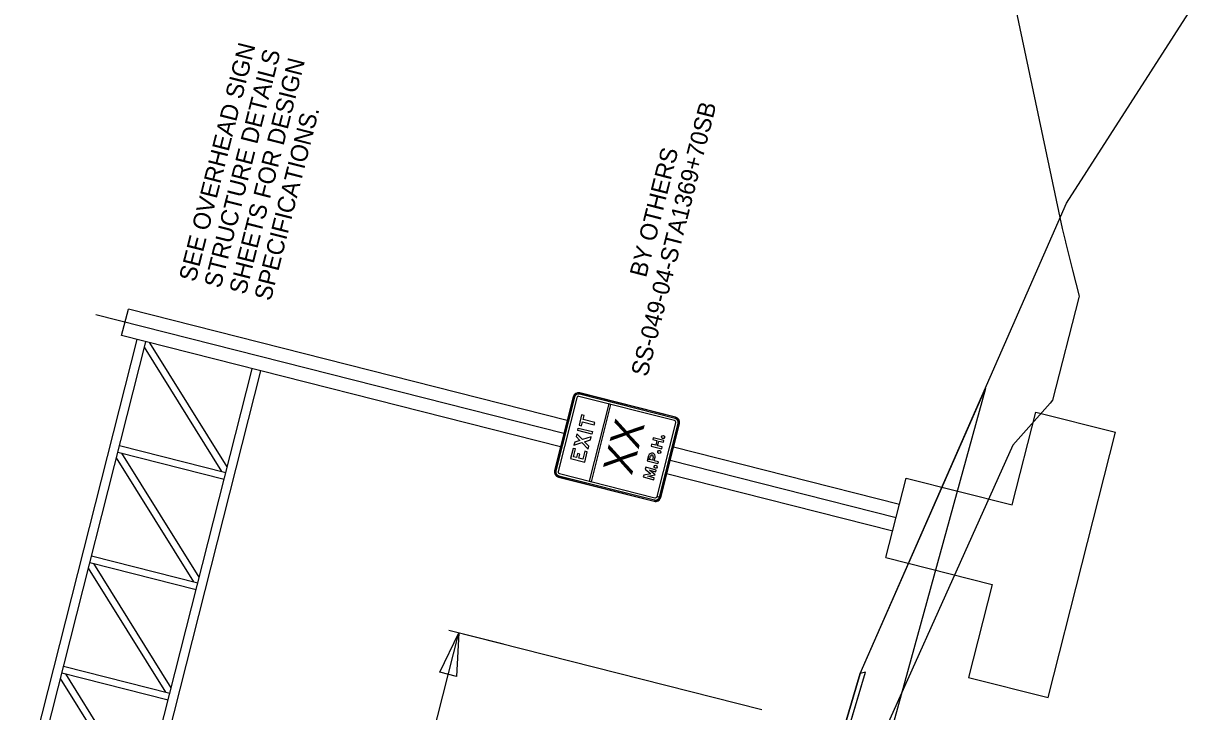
# Model space of a CAD drawing. Extents: x 670003 to 670131, y 737835 to 738003.
# Drawn here: x 670073.43 to 670116.21, y 737915.28 to 737940.42 of the extents above; entities that cross this region are included whole.
import ezdxf

# ---------------------------------------------------------------- set-up
doc = ezdxf.new("R2010")
doc.units = 0
for name, color, linetype in [('R_Alt Surface', 7, 'Continuous'), ('R_Exist Surface', 7, 'Continuous'), ('R_SIGN', 7, 'Continuous'), ('R_SIGN_ANNOT', 7, 'Continuous')]:
    doc.layers.add(name, color=color, linetype=linetype)

msp = doc.modelspace()

# ---------------------------------------------------------------- linework, layer by layer
at = {"layer": 'R_Alt Surface'}
msp.add_lwpolyline([(670102.433, 737911.395), (670103.999, 737916.672), (670111.535, 737933.847), (670116.209, 737941.135)], dxfattribs=at)
for points in [[(670108.568, 737927.085), (670102.543, 737905.177), (670102.018, 737905.311), (670102.212, 737905.963), (670100.911, 737905.679), (670104.184, 737916.713), (670103.999, 737916.672)], [(670102.433, 737911.395), (670102.595, 737911.354), (670104.184, 737916.713), (670103.999, 737916.672)]]:
    msp.add_lwpolyline(points, close=True, dxfattribs=at)
at = {"layer": 'R_Exist Surface'}
msp.add_lwpolyline([(670106.502, 737955.962), (670111.377, 737932.926), (670111.492, 737932.435), (670111.496, 737932.423), (670111.755, 737931.399), (670111.997, 737930.453), (670111.984, 737930.402), (670111.022, 737926.655), (670110.931, 737926.545), (670109.565, 737925.004), (670103.151, 737910.71), (670100.52, 737904.756), (670095.739, 737887.589), (670089.988, 737866.935), (670089.122, 737859.498), (670089.026, 737858.686), (670088.894, 737857.106), (670088.049, 737846.436), (670087.716, 737842.296), (670087.676, 737841.874), (670087.513, 737841.506), (670087.265, 737840.962)], dxfattribs=at)
at = {"layer": 'R_SIGN'}
for p, q in [((670093.172, 737925.432), (670076.077, 737929.768)), ((670077.021, 737929.012), (670077.267, 737929.982)), ((670093.295, 737925.916), (670077.267, 737929.982)), ((670073.434, 737912.507), (670077.583, 737928.87)), ((670093.049, 737924.947), (670077.021, 737929.012)), ((670073.757, 737912.425), (670077.906, 737928.788)), ((670080.683, 737924.049), (670077.855, 737928.586)), ((670080.874, 737924.216), (670078.046, 737928.752)), ((670077.635, 737911.442), (670081.784, 737927.804)), ((670077.951, 737911.332), (670082.107, 737927.722)), ((670093.514, 737926.778), (670092.831, 737924.086)), ((670093.522, 737926.776), (670092.839, 737924.084)), ((670093.562, 737926.765), (670092.879, 737924.074)), ((670093.643, 737926.745), (670092.96, 737924.053)), ((670093.522, 737926.776), (670093.522, 737926.776)), ((670097.214, 737925.907), (670093.724, 737926.793)), ((670097.234, 737925.988), (670093.744, 737926.873)), ((670093.754, 737926.913), (670093.754, 737926.913)), ((670097.244, 737926.028), (670093.754, 737926.913)), ((670097.246, 737926.036), (670093.756, 737926.921)), ((670094.812, 737926.517), (670094.097, 737923.697)), ((670094.812, 737926.517), (670094.097, 737923.697)), ((670094.812, 737926.517), (670094.097, 737923.697)), ((670094.178, 737923.676), (670094.893, 737926.496)), ((670094.178, 737923.676), (670094.893, 737926.496)), ((670094.178, 737923.676), (670094.893, 737926.496)), ((670094.893, 737926.496), (670094.812, 737926.517)), ((670094.893, 737926.496), (670094.812, 737926.517)), ((670094.893, 737926.496), (670094.812, 737926.517)), ((670097.246, 737926.036), (670094.885, 737926.634)), ((670097.244, 737926.028), (670097.244, 737926.028)), ((670109.551, 737922.825), (670110.411, 737926.218)), ((670110.411, 737926.218), (670113.319, 737925.48)), ((670096.58, 737923.136), (670097.262, 737925.827)), ((670096.66, 737923.116), (670097.343, 737925.807)), ((670096.701, 737923.105), (670097.383, 737925.796)), ((670096.709, 737923.103), (670097.391, 737925.794)), ((670097.383, 737925.796), (670097.383, 737925.796)), ((670110.861, 737915.787), (670113.319, 737925.48)), ((670076.884, 737924.755), (670080.761, 737923.771)), ((670076.945, 737924.997), (670080.822, 737924.014)), ((670079.851, 737920.183), (670077.023, 737924.719)), ((670096.439, 737924.583), (670096.408, 737924.459)), ((670105.428, 737922.839), (670097.173, 737924.933)), ((670079.66, 737920.016), (670076.833, 737924.553)), ((670096.476, 737924.441), (670096.507, 737924.566)), ((670105.305, 737922.355), (670097.05, 737924.448)), ((670092.839, 737924.084), (670092.839, 737924.084)), ((670092.976, 737923.845), (670096.466, 737922.959)), ((670092.978, 737923.852), (670092.978, 737923.853)), ((670092.978, 737923.852), (670096.468, 737922.967)), ((670092.988, 737923.893), (670096.478, 737923.007)), ((670093.009, 737923.973), (670096.498, 737923.088)), ((670105.182, 737921.87), (670096.927, 737923.964)), ((670104.936, 737920.901), (670105.673, 737923.809)), ((670105.673, 737923.809), (670109.551, 737922.825)), ((670094.097, 737923.697), (670094.178, 737923.676)), ((670094.097, 737923.697), (670094.178, 737923.676)), ((670094.097, 737923.697), (670094.178, 737923.676)), ((670096.468, 737922.967), (670096.468, 737922.967)), ((670096.66, 737923.115), (670096.579, 737923.135)), ((670096.58, 737923.136), (670096.66, 737923.116)), ((670096.701, 737923.105), (670096.7, 737923.105)), ((670096.709, 737923.102), (670096.701, 737923.105)), ((670096.701, 737923.105), (670096.709, 737923.103)), ((670075.922, 737920.964), (670079.8, 737919.981)), ((670104.936, 737920.901), (670108.813, 737919.917)), ((670078.637, 737915.983), (670075.81, 737920.52)), ((670075.861, 737920.722), (670079.738, 737919.738)), ((670078.828, 737916.149), (670076.001, 737920.686)), ((670108.813, 737919.917), (670107.953, 737916.525)), ((670074.9, 737916.931), (670078.777, 737915.948)), ((670077.615, 737911.95), (670074.787, 737916.487)), ((670074.838, 737916.688), (670078.716, 737915.705)), ((670077.806, 737912.116), (670074.978, 737916.653)), ((670107.953, 737916.525), (670110.861, 737915.787))]:
    msp.add_line(p, q, dxfattribs=at)
for points in [[(670093.818, 737925.72), (670093.854, 737925.864), (670094.281, 737925.756), (670094.303, 737925.844), (670093.877, 737925.953), (670093.913, 737926.097), (670093.823, 737926.119), (670093.727, 737925.743)], [(670093.818, 737925.72), (670093.854, 737925.864), (670094.281, 737925.756), (670094.303, 737925.844), (670093.877, 737925.953), (670093.913, 737926.097), (670093.823, 737926.119), (670093.727, 737925.743)], [(670093.818, 737925.72), (670093.854, 737925.864), (670094.281, 737925.756), (670094.303, 737925.844), (670093.877, 737925.953), (670093.913, 737926.097), (670093.823, 737926.119), (670093.727, 737925.743)], [(670094.195, 737925.417), (670093.678, 737925.548), (670093.7, 737925.637), (670094.217, 737925.506)], [(670094.195, 737925.417), (670093.678, 737925.548), (670093.7, 737925.637), (670094.217, 737925.506)], [(670094.195, 737925.417), (670093.678, 737925.548), (670093.7, 737925.637), (670094.217, 737925.506)], [(670094.056, 737924.869), (670094.082, 737924.974), (670093.926, 737925.137), (670094.141, 737925.206), (670094.168, 737925.311), (670093.855, 737925.211), (670093.647, 737925.428), (670093.621, 737925.323), (670093.758, 737925.18), (670093.569, 737925.119), (670093.542, 737925.014), (670093.829, 737925.106)], [(670094.056, 737924.869), (670094.082, 737924.974), (670093.926, 737925.137), (670094.141, 737925.206), (670094.168, 737925.311), (670093.855, 737925.211), (670093.647, 737925.428), (670093.621, 737925.323), (670093.758, 737925.18), (670093.569, 737925.119), (670093.542, 737925.014), (670093.829, 737925.106)], [(670094.056, 737924.869), (670094.082, 737924.974), (670093.926, 737925.137), (670094.141, 737925.206), (670094.168, 737925.311), (670093.855, 737925.211), (670093.647, 737925.428), (670093.621, 737925.323), (670093.758, 737925.18), (670093.569, 737925.119), (670093.542, 737925.014), (670093.829, 737925.106)], [(670096.571, 737925.179), (670096.527, 737925.005), (670096.375, 737925.043), (670096.359, 737924.977), (670096.746, 737924.878), (670096.763, 737924.945), (670096.595, 737924.987), (670096.639, 737925.162), (670096.807, 737925.119), (670096.824, 737925.185), (670096.436, 737925.283), (670096.42, 737925.217)], [(670096.571, 737925.179), (670096.527, 737925.005), (670096.375, 737925.043), (670096.359, 737924.977), (670096.746, 737924.878), (670096.763, 737924.945), (670096.595, 737924.987), (670096.639, 737925.162), (670096.807, 737925.119), (670096.824, 737925.185), (670096.436, 737925.283), (670096.42, 737925.217)], [(670096.571, 737925.179), (670096.527, 737925.005), (670096.375, 737925.043), (670096.359, 737924.977), (670096.746, 737924.878), (670096.763, 737924.945), (670096.595, 737924.987), (670096.639, 737925.162), (670096.807, 737925.119), (670096.824, 737925.185), (670096.436, 737925.283), (670096.42, 737925.217)], [(670093.938, 737924.785), (670093.865, 737924.497), (670093.721, 737924.534), (670093.76, 737924.686), (670093.669, 737924.709), (670093.631, 737924.557), (670093.529, 737924.583), (670093.602, 737924.871), (670093.512, 737924.893), (670093.416, 737924.517), (670093.933, 737924.386), (670094.029, 737924.762)], [(670093.938, 737924.785), (670093.865, 737924.497), (670093.721, 737924.534), (670093.76, 737924.686), (670093.669, 737924.709), (670093.631, 737924.557), (670093.529, 737924.583), (670093.602, 737924.871), (670093.512, 737924.893), (670093.416, 737924.517), (670093.933, 737924.386), (670094.029, 737924.762)], [(670093.938, 737924.785), (670093.865, 737924.497), (670093.721, 737924.534), (670093.76, 737924.686), (670093.669, 737924.709), (670093.631, 737924.557), (670093.529, 737924.583), (670093.602, 737924.871), (670093.512, 737924.893), (670093.416, 737924.517), (670093.933, 737924.386), (670094.029, 737924.762)], [(670096.243, 737923.874), (670096.505, 737923.925), (670096.299, 737924.095), (670096.533, 737924.036), (670096.55, 737924.102), (670096.162, 737924.201), (670096.145, 737924.134), (670096.349, 737923.965), (670096.089, 737923.913), (670096.072, 737923.847), (670096.46, 737923.748), (670096.477, 737923.815)], [(670096.243, 737923.874), (670096.505, 737923.925), (670096.299, 737924.095), (670096.533, 737924.036), (670096.55, 737924.102), (670096.162, 737924.201), (670096.145, 737924.134), (670096.349, 737923.965), (670096.089, 737923.913), (670096.072, 737923.847), (670096.46, 737923.748), (670096.477, 737923.815)], [(670096.243, 737923.874), (670096.505, 737923.925), (670096.299, 737924.095), (670096.533, 737924.036), (670096.55, 737924.102), (670096.162, 737924.201), (670096.145, 737924.134), (670096.349, 737923.965), (670096.089, 737923.913), (670096.072, 737923.847), (670096.46, 737923.748), (670096.477, 737923.815)]]:
    msp.add_lwpolyline(points, close=True, dxfattribs=at)
for points in [[(670096.27, 737924.626), (670096.221, 737924.435), (670096.609, 737924.337), (670096.626, 737924.403), (670096.476, 737924.441)], [(670096.27, 737924.626), (670096.238, 737924.502), (670096.306, 737924.484), (670096.338, 737924.609)], [(670096.27, 737924.626), (670096.238, 737924.502), (670096.306, 737924.484), (670096.338, 737924.609)], [(670096.439, 737924.583), (670096.408, 737924.459), (670096.238, 737924.502)], [(670096.439, 737924.583), (670096.408, 737924.459), (670096.238, 737924.502)], [(670096.408, 737924.459), (670096.306, 737924.484), (670096.338, 737924.609)], [(670096.238, 737924.502), (670096.221, 737924.435), (670096.609, 737924.337), (670096.626, 737924.403), (670096.476, 737924.441), (670096.507, 737924.566)], [(670096.238, 737924.502), (670096.221, 737924.435), (670096.609, 737924.337), (670096.626, 737924.403), (670096.476, 737924.441), (670096.507, 737924.566)]]:
    msp.add_lwpolyline(points, dxfattribs=at)
for centre, major_axis, ratio, start_param, end_param in [((670093.707, 737926.729), (-0.194, 0.049), 0.991667, 4.712389, 6.283185), ((670093.707, 737926.729), (-0.186, 0.047), 0.991667, 4.712389, 6.283185), ((670093.707, 737926.729), (-0.145, 0.037), 0.991667, 4.712389, 6.283185), ((670093.707, 737926.729), (-0.0646, 0.0164), 0.991667, 4.712389, 6.283185), ((670097.197, 737925.843), (-0.0646, 0.0164), 0.991667, 3.141593, 4.712389), ((670097.197, 737925.843), (-0.145, 0.037), 0.991667, 3.141593, 4.712389), ((670097.197, 737925.843), (-0.186, 0.047), 0.991667, 3.141593, 4.712389), ((670097.197, 737925.843), (-0.194, 0.049), 0.991667, 3.141593, 4.712389), ((670096.388, 737924.596), (-0.119, 0.03), 0.976792, 3.141593, 6.283185), ((670096.388, 737924.596), (-0.119, 0.03), 0.976792, 3.141593, 6.283185), ((670096.388, 737924.596), (-0.119, 0.03), 0.976792, 3.141593, 6.283185), ((670096.389, 737924.596), (-0.0509, 0.0129), 0.976792, 3.141593, 6.283185), ((670096.389, 737924.596), (-0.0509, 0.0129), 0.976792, 3.141593, 6.283185), ((670096.389, 737924.596), (-0.0509, 0.0129), 0.976792, 3.141593, 6.283185), ((670093.025, 737924.037), (-0.194, 0.049), 0.991667, 0, 1.570796), ((670093.025, 737924.037), (-0.186, 0.047), 0.991667, 0, 1.570796), ((670093.025, 737924.037), (-0.145, 0.037), 0.991667, 0, 1.570796), ((670093.025, 737924.037), (-0.0646, 0.0164), 0.991667, 0, 1.570796), ((670096.515, 737923.152), (-0.194, 0.049), 0.991667, 1.570796, 3.141593), ((670096.515, 737923.152), (-0.186, 0.047), 0.991667, 1.570796, 3.141593), ((670096.515, 737923.152), (-0.145, 0.037), 0.991667, 1.570796, 3.141593), ((670096.515, 737923.152), (-0.0646, 0.0164), 0.991667, 1.570796, 3.141593)]:
    msp.add_ellipse(centre, major_axis=major_axis, ratio=ratio, start_param=start_param, end_param=end_param, dxfattribs=at)
for centre in [(670096.795, 737925.304), (670096.795, 737925.304), (670096.795, 737925.304), (670096.658, 737924.763), (670096.658, 737924.763), (670096.658, 737924.763), (670096.521, 737924.221), (670096.521, 737924.221), (670096.521, 737924.221)]:
    msp.add_ellipse(centre, major_axis=(-0.0554, 0.0141), ratio=0.991667, dxfattribs=at)
at = {"layer": 'R_SIGN_ANNOT'}
for p, q in [((670090.97, 737917.737), (670088.971, 737918.244)), ((670100.405, 737915.344), (670089.025, 737918.23)), ((670086.978, 737908.86), (670089.334, 737918.152))]:
    msp.add_line(p, q, dxfattribs=at)
msp.add_lwpolyline([(670088.648, 737916.716), (670089.334, 737918.152), (670089.253, 737916.562)], close=True, dxfattribs=at)

# ---------------------------------------------------------------- texts
at = {"layer": 'R_SIGN'}
msp.add_text('XX', height=1.098, rotation=75.7686, dxfattribs=at).set_placement((670095.652, 737923.878))
at = {"layer": 'R_SIGN_ANNOT'}
for s, height, p in [('SEE OVERHEAD SIGN ', 0.63, (670079.716, 737930.948)), ('STRUCTURE DETAILS ', 0.63, (670080.632, 737930.715)), ('SHEETS FOR DESIGN ', 0.63, (670081.548, 737930.483)), ('SS-049-04-STA1369+70SB', 0.625, (670096.221, 737927.483)), ('SPECIFICATIONS.', 0.63, (670082.464, 737930.251)), ('BY OTHERS', 0.625, (670096.173, 737931.108))]:
    msp.add_text(s, height=height, rotation=75.7686, dxfattribs=at).set_placement(p)

doc.saveas('drawing.dxf')
